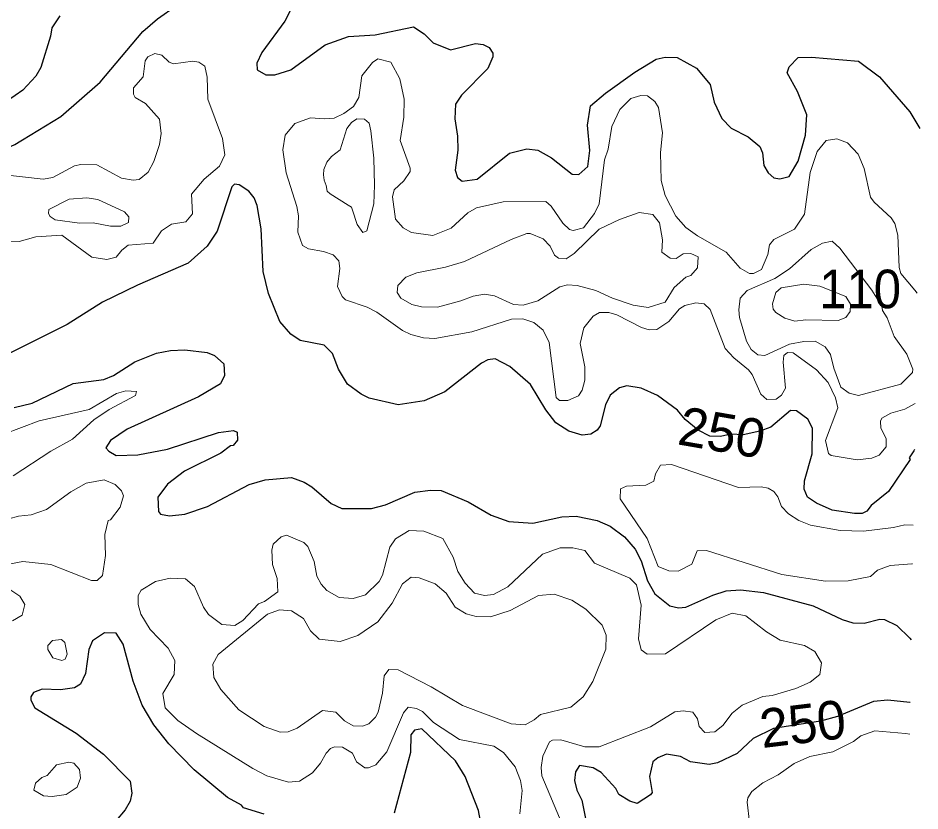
# Model space of a CAD drawing. Extents: x 763.2 to 816.8, y 7896.5 to 7952.7.
# Drawn here: x 812.488 to 816.225, y 7914.83 to 7918.117 of the extents above; entities that cross this region are included whole.
import ezdxf
from ezdxf.enums import TextEntityAlignment as Align

# ---------------------------------------------------------------- set-up
doc = ezdxf.new("R2010")
doc.units = 0
doc.header["$LTSCALE"] = 0.064
doc.layers.add('1', color=7, linetype='Continuous', lineweight=25)
doc.layers.add('2', color=7, linetype='Continuous', lineweight=13)
doc.layers.add('21', color=7, linetype='Continuous')
doc.layers.add('61', color=7, linetype='Continuous')

msp = doc.modelspace()

# ---------------------------------------------------------------- linework, layer by layer
at = {"layer": '1'}
for points in [[(812.6612, 7918.1262), (812.6276, 7918.0758), (812.6225, 7918.0414), (812.5819, 7917.9113), (812.5616, 7917.8754), (812.5074, 7917.8182), (812.4107, 7917.7513), (812.1978, 7917.6676), (812.1288, 7917.6462), (811.9989, 7917.5658), (811.9659, 7917.5216), (811.9609, 7917.4606), (811.9869, 7917.4409), (812.0978, 7917.4438), (812.3138, 7917.5205), (812.475, 7917.5927), (812.6647, 7917.7086), (812.8276, 7917.8509), (813.0051, 7918.0613), (813.0654, 7918.1132), (813.1443, 7918.1692)], [(813.6169, 7918.1498), (813.5939, 7918.1045)], [(813.5939, 7918.1045), (813.4976, 7917.9736), (813.4775, 7917.9304), (813.4791, 7917.9026), (813.5152, 7917.8813), (813.552, 7917.8813)], [(813.552, 7917.8813), (813.6187, 7917.9019), (813.7601, 7918.0058), (813.8577, 7918.0404), (813.9671, 7918.0473), (814.1265, 7918.0805), (814.1702, 7918.0508), (814.2087, 7918.0134), (814.2803, 7917.9849), (814.3828, 7918.0107), (814.4149, 7918.0076), (814.4402, 7917.9943), (814.4546, 7917.9719), (814.4551, 7917.9563), (814.434, 7917.9081), (814.3248, 7917.7968), (814.3005, 7917.7595), (814.2974, 7917.6995), (814.3089, 7917.6272), (814.3106, 7917.5695), (814.2993, 7917.4867), (814.3088, 7917.4561), (814.3277, 7917.4407), (814.39, 7917.4493), (814.5243, 7917.5572), (814.5965, 7917.5752), (814.642, 7917.5689), (814.699, 7917.537), (814.7846, 7917.4702), (814.8114, 7917.4678), (814.849, 7917.501), (814.8578, 7917.5681), (814.848, 7917.6724), (814.8602, 7917.7532), (814.9225, 7917.8059), (815.0435, 7917.8925), (815.1324, 7917.9459), (815.1692, 7917.955), (815.219, 7917.9527), (815.2992, 7917.9094), (815.3555, 7917.8415), (815.3727, 7917.7677), (815.4047, 7917.701), (815.443, 7917.6609), (815.5135, 7917.6246), (815.5617, 7917.5847), (815.5728, 7917.5575), (815.5781, 7917.5057), (815.5958, 7917.4752), (815.6195, 7917.4538), (815.645, 7917.4506), (815.6829, 7917.4595), (815.7208, 7917.5236), (815.7501, 7917.6313), (815.7564, 7917.7156), (815.7173, 7917.812), (815.6754, 7917.8898), (815.6829, 7917.9139), (815.7202, 7917.9528), (815.7758, 7917.955), (815.97, 7917.9376), (816.0569, 7917.8733), (816.1834, 7917.728), (816.225, 7917.6595)], [(816.2025, 7916.3277), (816.1994, 7916.3229), (816.1802, 7916.2938), (816.1844, 7916.2871), (816.0947, 7916.1549), (816.0232, 7916.0961), (816.0052, 7916.0726), (815.9861, 7916.0635), (815.9533, 7916.0624), (815.8613, 7916.0769), (815.7963, 7916.1062), (815.7594, 7916.1308), (815.7457, 7916.1646), (815.7468, 7916.1984), (815.7782, 7916.3107), (815.7799, 7916.4167), (815.7599, 7916.4545), (815.7139, 7916.4888), (815.6887, 7916.4899), (815.6065, 7916.4212), (815.5611, 7916.4041), (815.4928, 7916.3885), (815.442, 7916.3924), (815.399, 7916.3827), (815.3547, 7916.3843), (815.3054, 7916.4083), (815.2528, 7916.4524), (815.22, 7916.4913), (815.1374, 7916.5523), (815.0698, 7916.5827), (815.0106, 7916.5924), (814.9805, 7916.5839), (814.942, 7916.5536), (814.922, 7916.5137), (814.8993, 7916.4266), (814.8874, 7916.4092), (814.8611, 7916.3923), (814.825, 7916.3875), (814.7695, 7916.405), (814.7161, 7916.4387), (814.6754, 7916.4932), (814.6117, 7916.5984), (814.5256, 7916.6722), (814.4643, 7916.7041), (814.4342, 7916.7004), (814.4086, 7916.6869), (814.2563, 7916.568), (814.1709, 7916.5297), (814.0633, 7916.5141), (813.9431, 7916.5414), (813.9097, 7916.5574), (813.8533, 7916.5998), (813.8159, 7916.6617), (813.7914, 7916.7266), (813.7559, 7916.7613), (813.6575, 7916.7804), (813.6182, 7916.8068), (813.5728, 7916.8589), (813.5255, 7916.9756), (813.5038, 7917.066), (813.4953, 7917.2427), (813.4786, 7917.3394), (813.4657, 7917.3716), (813.4443, 7917.3994), (813.4036, 7917.4249), (813.3851, 7917.4288), (813.3737, 7917.4171), (813.3126, 7917.2329), (813.2715, 7917.1716), (813.193, 7917.1005), (812.9833, 7917.0102), (812.8381, 7916.9393), (812.691, 7916.846), (812.4487, 7916.7247)], [(812.4725, 7916.5027), (812.5462, 7916.5206), (812.7158, 7916.6021), (812.8428, 7916.6179), (812.8834, 7916.6352), (812.9714, 7916.6921), (813.0615, 7916.7273), (813.1191, 7916.7386), (813.1791, 7916.7421), (813.2719, 7916.7306), (813.3025, 7916.7183), (813.3409, 7916.6839), (813.3439, 7916.6354), (813.3271, 7916.6003), (813.2364, 7916.5469)], [(813.2364, 7916.5469), (812.9407, 7916.412), (812.8715, 7916.3662), (812.8517, 7916.3357), (812.864, 7916.3211), (812.8947, 7916.3034)], [(812.8947, 7916.3034), (812.9848, 7916.3061), (813.1068, 7916.3295), (813.3187, 7916.3988), (813.3807, 7916.4067), (813.3963, 7916.4), (813.3967, 7916.3664), (813.379, 7916.345), (813.3686, 7916.3439), (813.3277, 7916.3132), (813.1776, 7916.2388), (813.1071, 7916.1844), (813.0679, 7916.1306), (813.0697, 7916.0707), (813.0789, 7916.06), (813.1158, 7916.0536), (813.1793, 7916.061), (813.2726, 7916.0917), (813.4462, 7916.1833), (813.5118, 7916.2031), (813.6204, 7916.2128), (813.6729, 7916.1932), (813.7057, 7916.1735), (813.7858, 7916.105), (813.83, 7916.0845), (813.953, 7916.0833), (814.0107, 7916.0993), (814.1315, 7916.1516), (814.1972, 7916.1602), (814.2411, 7916.1591), (814.3526, 7916.1113), (814.448, 7916.0556), (814.5209, 7916.0306), (814.6203, 7916.0224), (814.7411, 7916.0486), (814.8003, 7916.0519), (814.8874, 7916.0342), (814.9417, 7916.0108), (815.0002, 7915.9669), (815.0449, 7915.9147), (815.0699, 7915.867), (815.0965, 7915.7834), (815.126, 7915.73), (815.1891, 7915.6808), (815.2244, 7915.6724), (815.2546, 7915.6742), (815.3663, 7915.7251), (815.4223, 7915.743), (815.4815, 7915.7462), (815.5768, 7915.7362), (815.782, 7915.6803), (815.9032, 7915.6236), (815.9473, 7915.6101), (815.9934, 7915.6082), (816.0592, 7915.6245), (816.0785, 7915.624), (816.1287, 7915.5988), (816.1825, 7915.5458), (816.1892, 7915.5392)], [(813.5083, 7914.8173), (813.4226, 7914.8436), (813.4142, 7914.854), (813.3562, 7914.8855), (813.2182, 7915.0012), (813.113, 7915.1083), (813.0507, 7915.1873), (813.002, 7915.2687), (812.9653, 7915.3687), (812.923, 7915.5216), (812.8941, 7915.5664), (812.8463, 7915.5685), (812.7963, 7915.5358), (812.7818, 7915.4996), (812.7674, 7915.4002), (812.7463, 7915.3558), (812.7221, 7915.3403), (812.6636, 7915.3324), (812.5875, 7915.3356), (812.5515, 7915.3209), (812.5407, 7915.3033), (812.5406, 7915.2891), (812.5577, 7915.2579), (812.7295, 7915.1529), (812.8419, 7915.0653), (812.953, 7914.9533), (812.9595, 7914.9039), (812.9529, 7914.8703), (812.9321, 7914.8348), (812.8946, 7914.7911)], [(816.1848, 7915.2798), (816.1825, 7915.28), (816.0921, 7915.2892), (816.033, 7915.2842), (815.8836, 7915.2213), (815.8134, 7915.2017), (815.6186, 7915.1713), (815.5335, 7915.1298), (815.4675, 7915.0683), (815.3866, 7915.0302), (815.3518, 7915.0232), (815.2744, 7915.0344), (815.2324, 7915.0563), (815.1743, 7915.0649), (815.1389, 7915.0509), (815.1177, 7915.0344), (815.1045, 7914.9732), (815.1156, 7914.9065), (815.109, 7914.8967), (815.0533, 7914.8609), (815.0232, 7914.8707), (814.978, 7914.8985), (814.9645, 7914.9227), (814.9047, 7914.9889), (814.8709, 7915.0082), (814.8142, 7915.0179), (814.7973, 7914.9918), (814.7939, 7914.9557), (814.8039, 7914.9157), (814.8236, 7914.8751), (814.8396, 7914.7987)], [(814.4092, 7914.7568), (814.3953, 7914.8325), (814.3413, 7914.9728), (814.3006, 7915.0379), (814.1609, 7915.1707), (814.131, 7915.1653), (814.1155, 7915.1452), (814.1146, 7915.0723), (814.0459, 7914.8209)]]:
    msp.add_lwpolyline(points, dxfattribs=at)
at = {"layer": '2'}
for points in [[(812.4067, 7917.1924), (812.4922, 7917.1909), (812.5624, 7917.2105), (812.669, 7917.2171), (812.794, 7917.1258), (812.8554, 7917.1166), (812.8941, 7917.1257), (812.9175, 7917.1552), (812.9447, 7917.1747), (813.0477, 7917.1842), (813.0829, 7917.2349), (813.124, 7917.2629), (813.1829, 7917.2715), (813.211, 7917.3051), (813.2067, 7917.3861), (813.2593, 7917.4492), (813.3231, 7917.5034), (813.3442, 7917.5498), (813.3345, 7917.6175), (813.2748, 7917.7806), (813.2718, 7917.8712), (813.2613, 7917.9178), (813.2376, 7917.9343), (813.2127, 7917.9385), (813.1319, 7917.9269), (813.1137, 7917.9342), (813.0833, 7917.9624), (813.0544, 7917.9697), (813.0255, 7917.9564), (813.0146, 7917.9394), (813.0061, 7917.8726), (812.9669, 7917.8273), (812.9665, 7917.8013), (812.9736, 7917.7873), (813.0159, 7917.7622), (813.0747, 7917.6973), (813.0812, 7917.6378), (813.0748, 7917.5925), (813.0513, 7917.5222), (813.0274, 7917.4776), (812.9892, 7917.4473), (812.9655, 7917.4441), (812.9165, 7917.4534), (812.8149, 7917.5077), (812.7487, 7917.5095), (812.7214, 7917.5045), (812.6323, 7917.4559), (812.5915, 7917.4489), (812.4206, 7917.4685)], [(816.2135, 7916.9767), (816.2032, 7916.9891), (816.1462, 7917.0578), (816.1383, 7917.0826), (816.1332, 7917.2164), (816.1208, 7917.2645), (816.1055, 7917.2893), (816.0348, 7917.3531), (816.0204, 7917.3738), (815.9936, 7917.4926), (815.9683, 7917.5529), (815.9254, 7917.5999), (815.8812, 7917.6164), (815.8363, 7917.6098), (815.7992, 7917.5641), (815.77, 7917.4767), (815.7468, 7917.3034), (815.705, 7917.2418), (815.619, 7917.1989), (815.6022, 7917.1767), (815.5952, 7917.1369), (815.569, 7917.0744), (815.5355, 7917.0584), (815.5183, 7917.0577), (815.4794, 7917.0802), (815.4218, 7917.1458), (815.3027, 7917.2142), (815.255, 7917.2489), (815.2129, 7917.296), (815.1688, 7917.3808), (815.1534, 7917.443), (815.1504, 7917.5589), (815.1586, 7917.6407), (815.1417, 7917.7459), (815.1264, 7917.7702), (815.0967, 7917.7939), (815.0684, 7917.7953), (815.0269, 7917.7834), (814.982, 7917.7375), (814.9481, 7917.6667), (814.9329, 7917.5728), (814.9186, 7917.5287), (814.896, 7917.3468), (814.8768, 7917.3065), (814.8306, 7917.2477), (814.7887, 7917.2355), (814.7725, 7917.2403), (814.7456, 7917.267), (814.6973, 7917.3365), (814.6747, 7917.3567), (814.4979, 7917.3551), (814.3881, 7917.3299), (814.351, 7917.3098), (814.2833, 7917.2462), (814.206, 7917.2157), (814.1186, 7917.228), (814.0831, 7917.2475), (814.0525, 7917.2835), (814.0393, 7917.3758), (814.0458, 7917.4048), (814.086, 7917.442), (814.1121, 7917.4811), (814.1129, 7917.4942), (814.0707, 7917.6089), (814.0869, 7917.7062), (814.0884, 7917.7805), (814.0705, 7917.8647), (814.0329, 7917.9341), (813.9789, 7917.9482), (813.9567, 7917.9328), (813.9131, 7917.8777), (813.9, 7917.7871), (813.878, 7917.7498), (813.8385, 7917.7208), (813.7978, 7917.7022), (813.7569, 7917.6987), (813.6999, 7917.7035), (813.6348, 7917.68), (813.5942, 7917.6312), (813.5858, 7917.5707), (813.5987, 7917.4748), (813.6433, 7917.3354), (813.6497, 7917.2967), (813.6476, 7917.2294), (813.6661, 7917.1734), (813.692, 7917.16), (813.7532, 7917.1494), (813.7943, 7917.1346), (813.8169, 7917.1102), (813.8207, 7917.0791), (813.8111, 7917.004), (813.8313, 7916.9628), (813.8446, 7916.9486), (813.9352, 7916.9182), (813.9753, 7916.8982)], [(814.3678, 7916.8164), (814.5322, 7916.8688), (814.5795, 7916.8704), (814.6254, 7916.8551), (814.6639, 7916.8235), (814.6881, 7916.7715), (814.7182, 7916.5443), (814.7317, 7916.5319), (814.7661, 7916.5308), (814.8097, 7916.551), (814.8257, 7916.5737), (814.8364, 7916.6163), (814.8364, 7916.6708), (814.8171, 7916.7678), (814.8317, 7916.8325), (814.8705, 7916.8814), (814.8966, 7916.8965), (814.9357, 7916.8964), (814.9691, 7916.886), (815.0712, 7916.8337), (815.1034, 7916.8244), (815.1342, 7916.8258), (815.1841, 7916.8584), (815.2284, 7916.912), (815.2513, 7916.9247), (815.2958, 7916.9361), (815.3314, 7916.9323), (815.3552, 7916.9083), (815.418, 7916.7477), (815.4544, 7916.7077), (815.5145, 7916.6587), (815.5296, 7916.6387), (815.5654, 7916.5584), (815.5899, 7916.5351), (815.6291, 7916.5372), (815.6518, 7916.5537), (815.6678, 7916.583), (815.6583, 7916.6906), (815.6612, 7916.7187), (815.6755, 7916.7304), (815.6993, 7916.7284), (815.7958, 7916.6587), (815.8442, 7916.6067), (815.8756, 7916.542), (815.8849, 7916.5006), (815.8341, 7916.3653), (815.8455, 7916.3121), (815.8568, 7916.3037), (815.9652, 7916.2854), (816.0262, 7916.292), (816.0554, 7916.3048), (816.0854, 7916.3391), (816.0853, 7916.3734), (816.0623, 7916.4166), (816.0609, 7916.4465), (816.0668, 7916.4583), (816.1046, 7916.4787), (816.1628, 7916.4952), (816.2058, 7916.5186)], [(813.9753, 7916.8982), (814.0812, 7916.8223), (814.116, 7916.8049), (814.1681, 7916.7912), (814.2152, 7916.7882), (814.3678, 7916.8164)], [(812.4683, 7916.2195), (812.6241, 7916.3218), (812.7131, 7916.3709), (812.8019, 7916.4511), (812.866, 7916.4938), (812.9749, 7916.5526), (812.9783, 7916.5693), (812.934, 7916.5712), (812.8953, 7916.5602), (812.7829, 7916.4939), (812.5753, 7916.4477), (812.4292, 7916.3913)], [(816.1973, 7916.0149), (816.1629, 7916.0162), (816.1157, 7916.0044), (815.9911, 7915.9896), (815.8948, 7915.9928), (815.7714, 7916.0154), (815.7233, 7916.0342), (815.6806, 7916.0623), (815.6517, 7916.0921), (815.6367, 7916.1324), (815.6192, 7916.1548), (815.5963, 7916.1682), (815.5671, 7916.1736), (815.4734, 7916.1705), (815.1957, 7916.2657), (815.1498, 7916.2631), (815.1292, 7916.2275), (815.1224, 7916.1973), (815.0895, 7916.1803), (815.0093, 7916.1762), (814.9846, 7916.165), (814.9828, 7916.1235), (815.0953, 7915.9596), (815.1397, 7915.8429), (815.1849, 7915.8251), (815.2236, 7915.8234), (815.2798, 7915.8534), (815.3014, 7915.9081), (815.3401, 7915.9103), (815.6523, 7915.8103), (815.8331, 7915.7825), (815.927, 7915.7841), (816.0197, 7915.8024), (816.0496, 7915.8278), (816.1013, 7915.8476), (816.1907, 7915.8538), (816.1945, 7915.8541)], [(812.4275, 7915.8491), (812.5078, 7915.8646), (812.6238, 7915.8514), (812.7918, 7915.7857), (812.816, 7915.7858), (812.8375, 7915.8066), (812.8506, 7915.8889), (812.8479, 7915.9761), (812.8618, 7916.0338), (812.8705, 7916.0374), (812.9106, 7916.0887), (812.9248, 7916.1357), (812.9167, 7916.1568), (812.8907, 7916.1836), (812.8442, 7916.203), (812.7697, 7916.1885), (812.7071, 7916.1525), (812.6062, 7916.0801), (812.5422, 7916.0569), (812.4896, 7916.0518), (812.4495, 7916.0404)], [(813.5398, 7915.9115), (813.5454, 7915.9354), (813.5788, 7915.967), (813.6001, 7915.973), (813.6717, 7915.9426), (813.6882, 7915.9264), (813.715, 7915.8643), (813.7256, 7915.804), (813.7445, 7915.7695), (813.7668, 7915.7446), (813.8182, 7915.7148), (813.8767, 7915.7101), (813.928, 7915.7254), (813.9846, 7915.7818), (813.9981, 7915.8068), (814.0291, 7915.924), (814.0516, 7915.9584), (814.1086, 7915.9925), (814.1692, 7915.9894), (814.2484, 7915.9591), (814.2911, 7915.882), (814.3109, 7915.8228), (814.3408, 7915.7739), (814.3788, 7915.7331), (814.4205, 7915.7231), (814.4574, 7915.7267), (814.5174, 7915.7594), (814.6614, 7915.8942), (814.7339, 7915.9203), (814.7869, 7915.9205), (814.8362, 7915.9104), (814.8765, 7915.8578), (815.0226, 7915.7954), (815.0499, 7915.7676), (815.0697, 7915.6836), (815.0586, 7915.5435), (815.0703, 7915.4982), (815.0947, 7915.4802), (815.171, 7915.4815), (815.3799, 7915.6225)], [(813.4845, 7915.6893), (813.5091, 7915.699), (813.5643, 7915.7388), (813.5612, 7915.7933), (813.5418, 7915.8516), (813.5398, 7915.9115)], [(814.5669, 7914.8184), (814.5766, 7914.9149), (814.57, 7914.9564), (814.5477, 7915.0134), (814.4994, 7915.0723), (814.4594, 7915.0987), (814.3174, 7915.1267), (814.21, 7915.1964), (814.1632, 7915.2423), (814.1389, 7915.255), (814.1049, 7915.2597), (814.0847, 7915.2363), (814.0154, 7915.0754), (813.9708, 7915.021), (813.9398, 7915.0087), (813.9245, 7915.009), (813.8904, 7915.0343), (813.8734, 7915.0702), (813.8325, 7915.0951), (813.7993, 7915.0954), (813.7824, 7915.0888), (813.7642, 7915.0702), (813.7419, 7915.0283), (813.7085, 7914.9882), (813.6547, 7914.9534), (813.6082, 7914.9489), (813.5184, 7914.9755), (813.4602, 7915.0054), (813.228, 7915.1505), (813.1504, 7915.2055), (813.0971, 7915.257), (813.0881, 7915.3172), (813.135, 7915.3956), (813.1373, 7915.4539), (813.1107, 7915.5044), (813.0349, 7915.5825), (812.9963, 7915.6454), (812.986, 7915.6861), (812.986, 7915.7233), (812.9976, 7915.7458), (813.0569, 7915.7818), (813.1181, 7915.7956), (813.1824, 7915.7922), (813.2196, 7915.7604), (813.2571, 7915.6754), (813.2774, 7915.644), (813.3326, 7915.6034), (813.3864, 7915.5985), (813.4197, 7915.6197), (813.4845, 7915.6893)], [(812.4653, 7915.6176), (812.5045, 7915.6419), (812.5156, 7915.6858), (812.495, 7915.7208), (812.4075, 7915.7784)], [(815.3799, 7915.6225), (815.4467, 7915.6504), (815.5037, 7915.6391), (815.5891, 7915.5722), (815.6463, 7915.5385), (815.7463, 7915.5162), (815.7892, 7915.4915), (815.8171, 7915.4434), (815.8104, 7915.3958), (815.7705, 7915.3637), (815.7107, 7915.3371), (815.6128, 7915.3092), (815.5735, 7915.3041), (815.4879, 7915.2682), (815.4467, 7915.2355), (815.4087, 7915.1848), (815.3757, 7915.1585), (815.3342, 7915.155), (815.31, 7915.1797), (815.303, 7915.2121), (815.2833, 7915.2397), (815.244, 7915.2449), (815.2099, 7915.241), (815.1081, 7915.1785), (814.8963, 7915.0956), (814.8371, 7915.0954), (814.7371, 7915.1249), (814.7025, 7915.1233), (814.6904, 7915.1164), (814.6622, 7915.057), (814.6558, 7915.0097), (814.6586, 7914.9756), (814.7426, 7914.7749)], [(816.1826, 7915.149), (816.1647, 7915.1506), (816.0379, 7915.1622), (815.9804, 7915.1413), (815.9492, 7915.1177), (815.8634, 7915.0747), (815.7692, 7915.0556), (815.7043, 7915.0263), (815.6369, 7914.9794), (815.5734, 7914.9461), (815.528, 7914.9106), (815.5121, 7914.8848), (815.5088, 7914.866), (815.5184, 7914.7841)]]:
    msp.add_lwpolyline(points, dxfattribs=at)
for points in [[(813.962, 7917.5359), (813.9504, 7917.6496), (813.9422, 7917.6804), (813.9231, 7917.6982), (813.8922, 7917.6985), (813.869, 7917.6838), (813.8507, 7917.6589), (813.8225, 7917.5711), (813.7874, 7917.5433), (813.7673, 7917.5189), (813.7551, 7917.4884), (813.7534, 7917.4671), (813.7568, 7917.4448), (813.7647, 7917.4223), (813.7688, 7917.3994), (813.7812, 7917.3875), (813.8563, 7917.3406), (813.869, 7917.3326), (813.8744, 7917.3211), (813.8929, 7917.2605), (813.916, 7917.2282), (813.9336, 7917.2346), (813.9619, 7917.3471), (813.9643, 7917.4242)], [(812.8183, 7917.365), (812.7736, 7917.3714), (812.7002, 7917.3665), (812.616, 7917.3233), (812.6146, 7917.3072), (812.6212, 7917.2941), (812.6419, 7917.2809), (812.7421, 7917.2664), (812.7993, 7917.2679), (812.8707, 7917.2537), (812.9146, 7917.2546), (812.9458, 7917.2693), (812.9466, 7917.2922), (812.9295, 7917.3142)], [(814.8818, 7916.9873), (814.8043, 7917.0081), (814.7641, 7917.0114), (814.733, 7917.0033), (814.6413, 7916.9452), (814.5808, 7916.9265), (814.5406, 7916.9295), (814.4617, 7916.9655), (814.421, 7916.9721), (814.3736, 7916.9641), (814.3231, 7916.9442), (814.2258, 7916.9182), (814.16, 7916.9197), (814.1193, 7916.9297), (814.074, 7916.9559), (814.0591, 7916.9788), (814.061, 7917.008), (814.0946, 7917.0431), (814.141, 7917.0613), (814.2586, 7917.0841), (814.3374, 7917.1072), (814.5315, 7917.1992), (814.5959, 7917.2234), (814.6094, 7917.2234), (814.6637, 7917.2018), (814.6931, 7917.1708), (814.7111, 7917.134), (814.7271, 7917.1218), (814.759, 7917.1188), (814.7917, 7917.1413), (814.8957, 7917.2416), (814.9795, 7917.2811), (815.0617, 7917.3108), (815.1185, 7917.3025), (815.1452, 7917.2678), (815.158, 7917.1976), (815.1553, 7917.1458), (815.1901, 7917.1208), (815.2154, 7917.1201), (815.2435, 7917.1393), (815.2754, 7917.1405), (815.3062, 7917.1274), (815.3032, 7917.0813), (815.2752, 7917.05), (815.2544, 7917.0431), (815.2068, 7917.0005), (815.1698, 7916.9396), (815.0983, 7916.9164), (815.0371, 7916.9271), (814.9516, 7916.9558)], [(815.8675, 7916.6653), (815.8539, 7916.7228), (815.8318, 7916.7538), (815.7911, 7916.7779), (815.7443, 7916.7762), (815.6839, 7916.7647), (815.5822, 7916.7175), (815.5529, 7916.721), (815.5252, 7916.7427), (815.5067, 7916.7772), (815.4774, 7916.8753), (815.4742, 7916.9075), (815.4803, 7916.9563), (815.5088, 7916.987), (815.6238, 7917.0374), (815.6844, 7917.0778), (815.7742, 7917.1569), (815.8208, 7917.184), (815.861, 7917.1917), (815.8936, 7917.1623), (816.0262, 7916.9885), (816.0668, 7916.922), (816.0693, 7916.9052), (816.089, 7916.8746), (816.1181, 7916.7971), (816.1709, 7916.7234), (816.1956, 7916.6615), (816.1934, 7916.647), (816.1456, 7916.599), (815.9701, 7916.5517), (815.9311, 7916.5614), (815.8978, 7916.5862)], [(815.6139, 7916.9318), (815.6285, 7916.9796), (815.6503, 7916.9991), (815.7436, 7917.0133), (815.81, 7917.0048), (815.9174, 7916.9621), (815.9373, 7916.9309), (815.9353, 7916.9006), (815.9173, 7916.875), (815.8861, 7916.8633), (815.7519, 7916.8663), (815.7072, 7916.8607), (815.6655, 7916.8721), (815.6278, 7916.8963), (815.6172, 7916.9099)], [(814.5273, 7915.6609), (814.6445, 7915.7227), (814.7099, 7915.7285), (814.7832, 7915.7037), (814.841, 7915.6672), (814.9082, 7915.6001), (814.9252, 7915.5592), (814.9235, 7915.5008), (814.869, 7915.3661), (814.8293, 7915.3036), (814.7785, 7915.2604), (814.653, 7915.2302), (814.6261, 7915.2072), (814.5892, 7915.1875), (814.5308, 7915.1908), (814.3297, 7915.2675), (814.2004, 7915.3452), (814.0627, 7915.4157), (814.0241, 7915.4167), (814.0051, 7915.3896), (813.9986, 7915.3187), (813.9806, 7915.2399), (813.9686, 7915.2186), (813.941, 7915.1916), (813.9146, 7915.1809), (813.8769, 7915.1827), (813.84, 7915.2043), (813.8041, 7915.2399), (813.75, 7915.2466), (813.6439, 7915.173), (813.6071, 7915.1579), (813.5743, 7915.1563), (813.5073, 7915.1799), (813.4023, 7915.2494), (813.3282, 7915.3332), (813.2997, 7915.3837), (813.295, 7915.4389), (813.3167, 7915.4787), (813.5214, 7915.6465), (813.5717, 7915.664), (813.6214, 7915.6602), (813.6713, 7915.6273), (813.6995, 7915.5764), (813.7363, 7915.5425), (813.823, 7915.5331), (813.8964, 7915.5573), (813.9791, 7915.6135), (814.0385, 7915.6908), (814.0807, 7915.7722), (814.1168, 7915.7986), (814.1495, 7915.797), (814.2164, 7915.7716), (814.2623, 7915.7335), (814.2996, 7915.6752), (814.3445, 7915.6466), (814.3861, 7915.6362), (814.4459, 7915.6345)], [(812.6676, 7915.5405), (812.6812, 7915.5277), (812.6918, 7915.4796), (812.6837, 7915.4593), (812.669, 7915.4538), (812.6318, 7915.4643), (812.6112, 7915.4997), (812.6121, 7915.5155), (812.6311, 7915.5373)], [(812.7335, 7914.9292), (812.7474, 7914.9657), (812.7425, 7915.0016), (812.7187, 7915.0281), (812.6978, 7915.0327), (812.6475, 7915.0207), (812.608, 7914.9772), (812.5867, 7914.9687), (812.5609, 7914.9455), (812.5538, 7914.9157), (812.5938, 7914.8921), (812.6292, 7914.89), (812.6874, 7914.8984)]]:
    msp.add_lwpolyline(points, close=True, dxfattribs=at)

# ---------------------------------------------------------------- texts
at = {"layer": '21', "width": 0.95}
msp.add_text('110', height=0.16, dxfattribs=at).set_placement((815.8075, 7916.9139))
at = {"layer": '61'}
for rotation, p in [(350.176, (815.3914, 7916.32)), (6.939, (815.7486, 7915.1121))]:
    msp.add_text('250', height=0.16, rotation=rotation, dxfattribs=at).set_placement(p, align=Align.CENTER)

doc.saveas('drawing.dxf')
